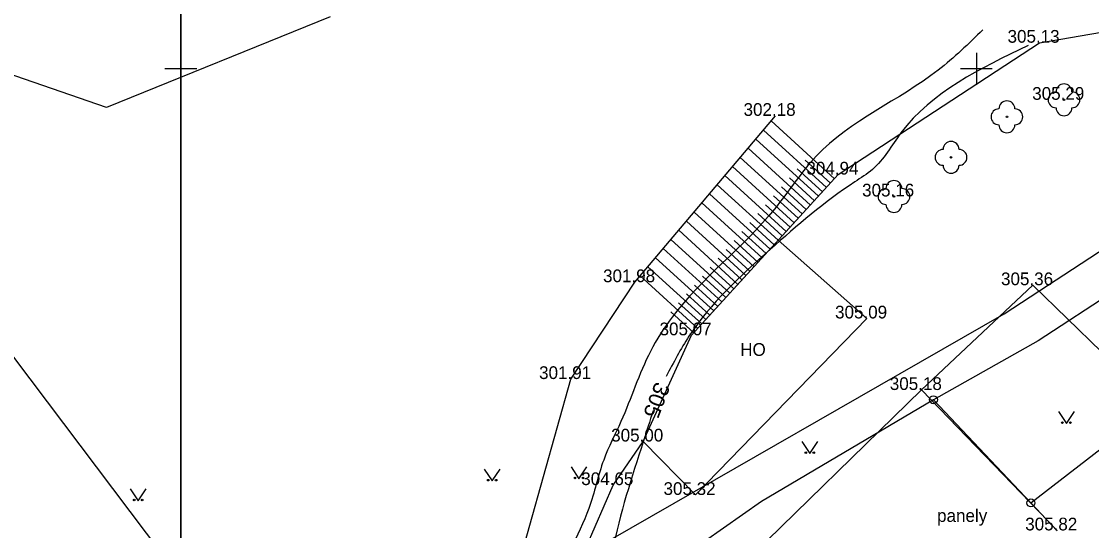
# Model space of a CAD drawing. Extents: x -504375 to -503125, y -1118000 to -1116474.
# Drawn here: x -503760 to -503692.8, y -1117179 to -1117147 of the extents above; entities that cross this region are included whole.
import ezdxf

# ---------------------------------------------------------------- set-up
doc = ezdxf.new("R2010")
doc.units = 0
for name, color, linetype in [('Chodníky', 7, 'Continuous'), ('Druhy povrchů', 7, 'Continuous'), ('Ploty', 7, 'Continuous'), ('Podkladové mapy', 7, 'Continuous'), ('Popisy budovy', 7, 'Continuous'), ('Stromy a keře', 7, 'Continuous'), ('Síť dekadická', 7, 'Continuous'), ('Vrstva 34', 7, 'Continuous'), ('Vrstva 48', 7, 'Continuous'), ('Výškopis', 7, 'Continuous'), ('Výšky bodů plotr', 7, 'Continuous')]:
    doc.layers.add(name, color=color, linetype=linetype)

msp = doc.modelspace()

# ---------------------------------------------------------------- linework, layer by layer
at = {"layer": 'Chodníky'}
msp.add_lwpolyline([(-503703.44, -1117170.2), (-503694.93, -1117179.03)], dxfattribs=at)
at = {"layer": 'Druhy povrchů'}
for points in [[(-503694.842, -1117171.55), (-503694.342, -1117172.3), (-503693.842, -1117171.55)], [(-503710.968, -1117173.441), (-503710.468, -1117174.191), (-503709.968, -1117173.441)], [(-503725.474, -1117175.031), (-503724.974, -1117175.781), (-503724.474, -1117175.031)], [(-503730.931, -1117175.169), (-503730.431, -1117175.919), (-503729.931, -1117175.169)], [(-503753.175, -1117176.413), (-503752.675, -1117177.163), (-503752.175, -1117176.413)]]:
    msp.add_lwpolyline(points, dxfattribs=at)
for centre in [(-503694.592, -1117172.25), (-503694.092, -1117172.25), (-503710.718, -1117174.141), (-503710.218, -1117174.141), (-503725.224, -1117175.731), (-503724.724, -1117175.731), (-503730.681, -1117175.869), (-503730.181, -1117175.869), (-503752.925, -1117177.113), (-503752.425, -1117177.113)]:
    msp.add_circle(centre, 0.05, dxfattribs=at)
at = {"layer": 'Ploty'}
for points in [[(-503720.95, -1117173.44), (-503717.66, -1117176.8), (-503706.88, -1117165.7), (-503712.457, -1117160.787)], [(-503692.13, -1117167.81), (-503696.45, -1117163.61), (-503703.44, -1117170.2), (-503714.91, -1117181.39), (-503714.504, -1117181.831)]]:
    msp.add_lwpolyline(points, dxfattribs=at)
at = {"layer": 'Podkladové mapy'}
for p, q in [((-503698.26, -1117165.42), (-503646.84, -1117131.67)), ((-503646.73, -1117134.84), (-503696.12, -1117167.1)), ((-503696.57, -1117177.3), (-503650.01, -1117141.08)), ((-503740.61, -1117146.74), (-503754.67, -1117152.43)), ((-503754.67, -1117152.43), (-503765.88, -1117148.58)), ((-503750.22, -1117181.77), (-503763.38, -1117164.31)), ((-503724.24, -1117180.33), (-503698.26, -1117165.42)), ((-503696.12, -1117167.1), (-503702.7, -1117170.81)), ((-503702.7, -1117170.81), (-503713.51, -1117177.21)), ((-503696.57, -1117177.3), (-503702.7, -1117170.81)), ((-503713.51, -1117177.21), (-503720.3, -1117181.97)), ((-503694.92, -1117179.05), (-503696.57, -1117177.3))]:
    msp.add_line(p, q, dxfattribs=at)
for centre, radius in [((-503702.7, -1117170.81), 0.25), ((-503702.7, -1117170.81), 0.005), ((-503696.57, -1117177.3), 0.25), ((-503696.57, -1117177.3), 0.005)]:
    msp.add_circle(centre, radius, dxfattribs=at)
at = {"layer": 'Stromy a keře'}
for centre in [(-503694.49, -1117151.95), (-503698.08, -1117153.02), (-503701.59, -1117155.57), (-503705.18, -1117158.03)]:
    msp.add_circle(centre, 0.05, dxfattribs=at)
for centre, start, end in [((-503694.99, -1117151.95), 90, 270), ((-503694.49, -1117151.45), 0, 180), ((-503693.99, -1117151.95), 270, 90), ((-503698.08, -1117152.52), 0, 180), ((-503698.58, -1117153.02), 90, 270), ((-503697.58, -1117153.02), 270, 90), ((-503694.49, -1117152.45), 180, 0), ((-503698.08, -1117153.52), 180, 0), ((-503701.59, -1117155.07), 0, 180), ((-503702.09, -1117155.57), 90, 270), ((-503701.09, -1117155.57), 270, 90), ((-503701.59, -1117156.07), 180, 0), ((-503705.68, -1117158.03), 90, 270), ((-503705.18, -1117157.53), 0, 180), ((-503704.68, -1117158.03), 270, 90), ((-503705.18, -1117158.53), 180, 0)]:
    msp.add_arc(centre, 0.5, start, end, dxfattribs=at)
at = {"layer": 'Síť dekadická'}
for points in [[(-503750, -1117000), (-503750, -1117500), (-504375, -1117500), (-504375, -1117000)], [(-503125, -1117000), (-503125, -1117500), (-503750, -1117500), (-503750, -1117000)]]:
    msp.add_lwpolyline(points, close=True, dxfattribs=at)
at = {"layer": 'Vrstva 34'}
for p, q in [((-503750, -1117149), (-503750, -1117151)), ((-503700, -1117149), (-503700, -1117151)), ((-503749, -1117150), (-503751, -1117150)), ((-503699, -1117150), (-503701, -1117150))]:
    msp.add_line(p, q, dxfattribs=at)
msp.add_lwpolyline([(-503750, -1116754.229), (-503750, -1117230.829)], dxfattribs=at)
at = {"layer": 'Vrstva 48'}
for points in [[(-503699.583, -1117147.544), (-503702.393, -1117150.08), (-503710.06, -1117155.491), (-503712.693, -1117158.826), (-503719.127, -1117165.624), (-503720.48, -1117167.771), (-503722.339, -1117172.188), (-503723.42, -1117174.604), (-503724.357, -1117177.651), (-503726.167, -1117182.804), (-503724.848, -1117186.843), (-503721.897, -1117191.523)], [(-503696.744, -1117148.536), (-503704.74, -1117154.037), (-503706.533, -1117156.329), (-503707.644, -1117157.114), (-503712.962, -1117161.367), (-503718.063, -1117166.817), (-503719.488, -1117169.348)], [(-503720.316, -1117171.519), (-503720.936, -1117173.456), (-503722.881, -1117187.116), (-503721.291, -1117191.092)]]:
    msp.add_spline(points, degree=3, dxfattribs=at)
at = {"layer": 'Výškopis'}
for p, q in [((-503708.917, -1117156.91), (-503712.897, -1117153.276)), ((-503709.423, -1117157.464), (-503713.381, -1117153.85)), ((-503709.929, -1117158.018), (-503713.865, -1117154.423)), ((-503710.434, -1117158.571), (-503714.349, -1117154.997)), ((-503711.446, -1117159.679), (-503715.318, -1117156.144)), ((-503710.94, -1117159.125), (-503714.834, -1117155.571)), ((-503709.17, -1117157.187), (-503710.758, -1117155.737)), ((-503711.951, -1117160.233), (-503715.802, -1117156.717)), ((-503710.181, -1117158.294), (-503711.752, -1117156.861)), ((-503709.676, -1117157.741), (-503711.255, -1117156.299)), ((-503712.457, -1117160.787), (-503716.286, -1117157.291)), ((-503710.687, -1117158.848), (-503712.249, -1117157.423)), ((-503712.963, -1117161.341), (-503716.77, -1117157.865)), ((-503711.193, -1117159.402), (-503712.746, -1117157.984)), ((-503713.468, -1117161.895), (-503717.254, -1117158.438)), ((-503711.698, -1117159.956), (-503713.243, -1117158.546)), ((-503714.48, -1117163.003), (-503718.223, -1117159.585)), ((-503713.974, -1117162.449), (-503717.739, -1117159.012)), ((-503712.204, -1117160.51), (-503713.74, -1117159.108)), ((-503714.985, -1117163.556), (-503718.707, -1117160.159)), ((-503713.215, -1117161.618), (-503714.734, -1117160.231)), ((-503712.71, -1117161.064), (-503714.237, -1117159.67)), ((-503715.491, -1117164.11), (-503719.191, -1117160.732)), ((-503713.721, -1117162.172), (-503715.231, -1117160.793)), ((-503715.997, -1117164.664), (-503719.675, -1117161.306)), ((-503714.227, -1117162.726), (-503715.728, -1117161.355)), ((-503716.502, -1117165.218), (-503720.159, -1117161.879)), ((-503714.732, -1117163.279), (-503716.225, -1117161.916)), ((-503717.008, -1117165.772), (-503720.644, -1117162.453)), ((-503715.238, -1117163.833), (-503716.722, -1117162.478)), ((-503717.514, -1117166.326), (-503721.128, -1117163.027)), ((-503716.249, -1117164.941), (-503717.717, -1117163.602)), ((-503715.744, -1117164.387), (-503717.22, -1117163.04)), ((-503716.755, -1117165.495), (-503718.214, -1117164.163)), ((-503717.261, -1117166.049), (-503718.711, -1117164.725)), ((-503717.766, -1117166.603), (-503719.208, -1117165.287))]:
    msp.add_line(p, q, dxfattribs=at)
for points in [[(-503722.83, -1117176.18), (-503720.95, -1117173.44), (-503717.91, -1117166.76), (-503708.68, -1117156.65), (-503696.04, -1117148.36), (-503679.24, -1117145.46), (-503671.99, -1117142.04), (-503661.82, -1117146.69)], [(-503721.46, -1117163.42), (-503712.63, -1117152.96)], [(-503722.507, -1117192.312), (-503727.35, -1117187.23), (-503728.93, -1117181.76), (-503725.48, -1117169.51), (-503721.46, -1117163.42)], [(-503725.25, -1117183.19), (-503725.66, -1117182.69), (-503722.83, -1117176.18)]]:
    msp.add_lwpolyline(points, dxfattribs=at)

# ---------------------------------------------------------------- texts
at = {"layer": 'Druhy povrchů'}
msp.add_text('panely', height=0.8, dxfattribs=at).set_placement((-503702.469, -1117178.497))
at = {"layer": 'Popisy budovy'}
msp.add_text('HO', height=0.8, dxfattribs=at).set_placement((-503714.841, -1117168.054))
at = {"layer": 'Vrstva 48'}
msp.add_text('305', height=1, rotation=249.31529, dxfattribs=at).set_placement((-503720.161, -1117169.628))
at = {"layer": 'Výšky bodů plotr'}
for s, p in [('305.13 ', (-503698.04, -1117148.36)), ('305.29 ', (-503696.49, -1117151.95)), ('302.18 ', (-503714.63, -1117152.96)), ('304.94 ', (-503710.68, -1117156.65)), ('305.16 ', (-503707.18, -1117158.03)), ('301.98 ', (-503723.46, -1117163.42)), ('305.36 ', (-503698.45, -1117163.61)), ('305.09 ', (-503708.88, -1117165.7)), ('305.07 ', (-503719.91, -1117166.76)), ('301.91 ', (-503727.48, -1117169.51)), ('305.18 ', (-503705.44, -1117170.2)), ('305.00 ', (-503722.95, -1117173.44)), ('304.65 ', (-503724.83, -1117176.18)), ('305.32 ', (-503719.66, -1117176.8)), ('305.82 ', (-503696.93, -1117179.03))]:
    msp.add_text(s, height=0.8, dxfattribs=at).set_placement(p)

doc.saveas('drawing.dxf')
